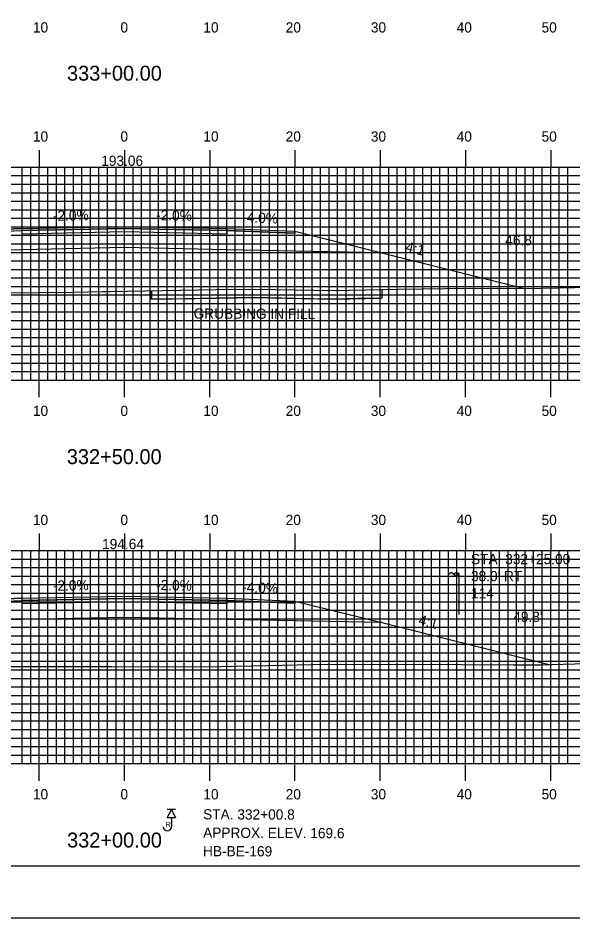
# Model space of a CAD drawing. Extents: x 1822785 to 1823129, y 442591 to 442811.
# Drawn here: x 1822938.8 to 1823003.9, y 442590.5 to 442696.2 of the extents above; entities that cross this region are included whole.
import ezdxf

# ---------------------------------------------------------------- set-up
doc = ezdxf.new("R2010")
doc.units = 0
for name, color, linetype in [('ANNOTATION', 7, 'Continuous'), ('BORDER', 7, 'Continuous'), ('BORING - REFUSAL', 7, 'Continuous'), ('D_Drainage_Text', 7, 'Continuous'), ('D_Roadway_Centerline', 7, 'Continuous'), ('D_Roadway_Centerline_Text', 7, 'Continuous'), ('D_Roadway_Edge_Shoulder', 7, 'Continuous'), ('D_Roadway_Edge_TW', 7, 'Continuous'), ('D_Roadway_Pavement', 7, 'Continuous'), ('D_Roadway_SlopeLines', 7, 'Continuous'), ('D_Roadway_SubGrade', 7, 'Continuous'), ('D_Text_Standard', 7, 'Continuous'), ('D_Utilities_Pole_Joint', 7, 'Continuous'), ('GRUBBING IN FILL', 7, 'Continuous'), ('H_V ANNOTATION', 7, 'Continuous'), ('MAJOR', 7, 'Continuous'), ('MINOR', 7, 'Continuous'), ('PLOT BOUNDARY', 7, 'Continuous'), ('S_Roadway_Centerline', 7, 'Continuous')]:
    doc.layers.add(name, color=color, linetype=linetype)

msp = doc.modelspace()

# ---------------------------------------------------------------- linework, layer by layer
at = {"layer": 'BORDER'}
msp.add_lwpolyline([(1822801.68, 442596.67), (1823121.68, 442596.67), (1823121.68, 442806.67), (1822801.68, 442806.67)], close=True, dxfattribs=at)
at = {"layer": 'BORING - REFUSAL'}
for p, q in [((1822957.26, 442603.27), (1822956.3, 442603.27)), ((1822956.78, 442602.31), (1822956.78, 442601.25))]:
    msp.add_line(p, q, dxfattribs=at)
msp.add_lwpolyline([(1822956.78, 442603.27), (1822957.26, 442602.31), (1822956.3, 442602.31)], close=True, dxfattribs=at)
msp.add_arc((1822956.3, 442601.25), 0.485, 180, 0, dxfattribs=at)
at = {"layer": 'D_Roadway_Centerline'}
for points in [[(1822903.76, 442662.99), (1822919.28, 442668.16), (1822921.11, 442668.62), (1822931.28, 442671.16), (1822939.28, 442671.48), (1822951.28, 442671.72), (1822963.28, 442671.48), (1822971.28, 442671.16), (1822981.46, 442668.62), (1822998.04, 442664.47)], [(1822902.83, 442619.27), (1822919.28, 442624.75), (1822921.11, 442625.21), (1822931.28, 442627.75), (1822939.28, 442628.07), (1822951.28, 442628.31), (1822963.28, 442628.07), (1822971.28, 442627.75), (1822981.46, 442625.21), (1823001.12, 442620.29)]]:
    msp.add_lwpolyline(points, dxfattribs=at)
at = {"layer": 'D_Roadway_Edge_Shoulder'}
for points in [[(1822939.28, 442671.48), (1822931.28, 442671.16), (1822931.28, 442670.91), (1822939.28, 442671.23)], [(1822963.28, 442671.48), (1822971.28, 442671.16), (1822971.28, 442670.91), (1822963.28, 442671.23)], [(1822939.28, 442628.07), (1822931.28, 442627.75), (1822931.28, 442627.5), (1822939.28, 442627.82)], [(1822963.28, 442628.07), (1822971.28, 442627.75), (1822971.28, 442627.5), (1822963.28, 442627.82)]]:
    msp.add_lwpolyline(points, close=True, dxfattribs=at)
at = {"layer": 'D_Roadway_Edge_TW'}
for points in [[(1822939.28, 442671.23), (1822939.28, 442671.48), (1822951.28, 442671.72), (1822963.28, 442671.48), (1822963.28, 442671.23), (1822951.28, 442671.47)], [(1822939.28, 442627.82), (1822939.28, 442628.07), (1822951.28, 442628.31), (1822963.28, 442628.07), (1822963.28, 442627.82), (1822951.28, 442628.06)]]:
    msp.add_lwpolyline(points, close=True, dxfattribs=at)
at = {"layer": 'D_Roadway_Pavement'}
for points in [[(1822939.28, 442670.82), (1822939.28, 442671.23), (1822951.28, 442671.47), (1822963.28, 442671.23), (1822963.28, 442670.82), (1822951.28, 442671.06)], [(1822939.28, 442627.4), (1822939.28, 442627.82), (1822951.28, 442628.06), (1822963.28, 442627.82), (1822963.28, 442627.4), (1822951.28, 442627.64)]]:
    msp.add_lwpolyline(points, close=True, dxfattribs=at)
at = {"layer": 'D_Roadway_SlopeLines'}
for points in [[(1822971.28, 442671.16), (1822981.46, 442668.62), (1822998.04, 442664.47)], [(1822971.28, 442627.75), (1822981.46, 442625.21), (1823001.12, 442620.29)]]:
    msp.add_lwpolyline(points, dxfattribs=at)
at = {"layer": 'D_Roadway_SubGrade'}
for points in [[(1822939.28, 442668.98), (1822921.11, 442668.62), (1822931.28, 442671.16), (1822931.28, 442670.91), (1822939.28, 442671.23), (1822951.28, 442671.47), (1822963.28, 442671.23), (1822971.28, 442670.91), (1822971.28, 442671.16), (1822981.46, 442668.62), (1822963.28, 442668.98), (1822951.28, 442669.22)], [(1822939.28, 442625.57), (1822921.11, 442625.21), (1822931.28, 442627.75), (1822931.28, 442627.5), (1822939.28, 442627.82), (1822951.28, 442628.06), (1822963.28, 442627.82), (1822971.28, 442627.5), (1822971.28, 442627.75), (1822981.46, 442625.21), (1822963.28, 442625.57), (1822951.28, 442625.81)]]:
    msp.add_lwpolyline(points, close=True, dxfattribs=at)
at = {"layer": 'D_Utilities_Pole_Joint'}
for p, q in [((1822989.28, 442630.91), (1822989.44, 442631.02)), ((1822989.75, 442631.02), (1822989.91, 442630.91)), ((1822990.06, 442631.02), (1822989.91, 442630.91)), ((1822990.53, 442630.91), (1822990.38, 442631.02)), ((1822989.28, 442626.15), (1822989.28, 442630.91)), ((1822989.91, 442630.91), (1822990.06, 442630.8)), ((1822990.38, 442630.8), (1822990.53, 442630.91)), ((1822990.53, 442626.15), (1822990.53, 442630.91))]:
    msp.add_line(p, q, dxfattribs=at)
for centre, start, end in [((1822989.59, 442630.8), 90, 125.2644), ((1822989.59, 442630.8), 54.7356, 90), ((1822990.22, 442630.8), 90, 125.2644), ((1822990.22, 442630.8), 54.7356, 90), ((1822990.22, 442631.02), 234.7356, 270), ((1822990.22, 442631.02), 270, 305.2644)]:
    msp.add_arc(centre, 0.271, start, end, dxfattribs=at)
at = {"layer": 'GRUBBING IN FILL'}
for p, q in [((1822954.46, 442664.16), (1822954.46, 442663.16)), ((1822954.46, 442664.16), (1822954.46, 442663.16)), ((1822981.46, 442664.31), (1822981.46, 442663.31)), ((1822981.46, 442664.31), (1822981.46, 442663.31))]:
    msp.add_line(p, q, dxfattribs=at)
msp.add_lwpolyline([(1822954.46, 442664.16), (1822955.79, 442664.19), (1822962.02, 442664.3), (1822966.67, 442664.36), (1822971.21, 442664.27), (1822975.75, 442664.19), (1822979.59, 442664.27), (1822981.46, 442664.31), (1822981.46, 442663.31), (1822978.6, 442663.25), (1822975.75, 442663.19), (1822971.21, 442663.27), (1822966.67, 442663.36), (1822964.35, 442663.33), (1822962.04, 442663.3), (1822958.25, 442663.23), (1822954.46, 442663.16)], close=True, dxfattribs=at)
msp.add_lwpolyline([(1822954.46, 442664.16), (1822955.79, 442664.19), (1822962.02, 442664.3), (1822966.67, 442664.36), (1822971.21, 442664.27), (1822975.75, 442664.19), (1822979.59, 442664.27), (1822981.46, 442664.31), (1822981.46, 442663.31), (1822978.6, 442663.25), (1822975.75, 442663.19), (1822971.21, 442663.27), (1822966.67, 442663.36), (1822964.35, 442663.33), (1822962.04, 442663.3), (1822958.25, 442663.23), (1822954.46, 442663.16)], close=True, dxfattribs=at)
msp.add_lwpolyline([(1822954.46, 442663.16), (1822962.04, 442663.3), (1822966.67, 442663.36), (1822975.75, 442663.19), (1822981.46, 442663.31)], dxfattribs=at)
msp.add_lwpolyline([(1822954.46, 442663.16), (1822962.04, 442663.3), (1822966.67, 442663.36), (1822975.75, 442663.19), (1822981.46, 442663.31)], dxfattribs=at)
at = {"layer": 'MAJOR'}
for p, q in [((1822941.28, 442680.67), (1822941.28, 442678.67)), ((1822951.28, 442680.67), (1822951.28, 442678.67)), ((1822961.28, 442680.67), (1822961.28, 442678.67)), ((1822971.28, 442680.67), (1822971.28, 442678.67)), ((1822981.28, 442680.67), (1822981.28, 442678.67)), ((1822991.28, 442680.67), (1822991.28, 442678.67)), ((1823001.28, 442680.67), (1823001.28, 442678.67)), ((1822811.28, 442678.67), (1823091.28, 442678.67)), ((1822811.28, 442678.67), (1823091.28, 442678.67)), ((1822941.28, 442653.67), (1822941.28, 442678.67)), ((1822951.28, 442653.67), (1822951.28, 442678.67)), ((1822961.28, 442653.67), (1822961.28, 442678.67)), ((1822971.28, 442653.67), (1822971.28, 442678.67)), ((1822981.28, 442653.67), (1822981.28, 442678.67)), ((1822991.28, 442653.67), (1822991.28, 442678.67)), ((1823001.28, 442653.67), (1823001.28, 442678.67)), ((1822811.28, 442673.67), (1823091.28, 442673.67)), ((1822811.28, 442668.67), (1823091.28, 442668.67)), ((1822811.28, 442663.67), (1823091.28, 442663.67)), ((1822811.28, 442658.67), (1823091.28, 442658.67)), ((1822811.28, 442653.67), (1823091.28, 442653.67)), ((1822811.28, 442653.67), (1823091.28, 442653.67)), ((1822941.28, 442651.66), (1822941.28, 442653.67)), ((1822951.28, 442651.66), (1822951.28, 442653.67)), ((1822961.28, 442651.66), (1822961.28, 442653.67)), ((1822971.28, 442651.66), (1822971.28, 442653.67)), ((1822981.28, 442651.66), (1822981.28, 442653.67)), ((1822991.28, 442651.66), (1822991.28, 442653.67)), ((1823001.28, 442651.66), (1823001.28, 442653.67)), ((1822941.28, 442635.67), (1822941.28, 442633.67)), ((1822951.28, 442635.67), (1822951.28, 442633.67)), ((1822961.28, 442635.67), (1822961.28, 442633.67)), ((1822971.28, 442635.67), (1822971.28, 442633.67)), ((1822981.28, 442635.67), (1822981.28, 442633.67)), ((1822991.28, 442635.67), (1822991.28, 442633.67)), ((1823001.28, 442635.67), (1823001.28, 442633.67)), ((1822811.28, 442633.67), (1823091.28, 442633.67)), ((1822811.28, 442633.67), (1823091.28, 442633.67)), ((1822941.28, 442608.67), (1822941.28, 442633.67)), ((1822951.28, 442608.67), (1822951.28, 442633.67)), ((1822961.28, 442608.67), (1822961.28, 442633.67)), ((1822971.28, 442608.67), (1822971.28, 442633.67)), ((1822981.28, 442608.67), (1822981.28, 442633.67)), ((1822991.28, 442608.67), (1822991.28, 442633.67)), ((1823001.28, 442608.67), (1823001.28, 442633.67)), ((1822811.28, 442628.67), (1823091.28, 442628.67)), ((1822811.28, 442623.67), (1823091.28, 442623.67)), ((1822811.28, 442618.67), (1823091.28, 442618.67)), ((1822811.28, 442613.67), (1823091.28, 442613.67)), ((1822811.28, 442608.67), (1823091.28, 442608.67)), ((1822811.28, 442608.67), (1823091.28, 442608.67)), ((1822941.28, 442606.66), (1822941.28, 442608.67)), ((1822951.28, 442606.66), (1822951.28, 442608.67)), ((1822961.28, 442606.66), (1822961.28, 442608.67)), ((1822971.28, 442606.66), (1822971.28, 442608.67)), ((1822981.28, 442606.66), (1822981.28, 442608.67)), ((1822991.28, 442606.66), (1822991.28, 442608.67)), ((1823001.28, 442606.66), (1823001.28, 442608.67))]:
    msp.add_line(p, q, dxfattribs=at)
at = {"layer": 'MINOR'}
for p, q in [((1822939.28, 442653.67), (1822939.28, 442678.67)), ((1822940.28, 442653.67), (1822940.28, 442678.67)), ((1822942.28, 442653.67), (1822942.28, 442678.67)), ((1822943.28, 442653.67), (1822943.28, 442678.67)), ((1822944.28, 442653.67), (1822944.28, 442678.67)), ((1822945.28, 442653.67), (1822945.28, 442678.67)), ((1822946.28, 442653.67), (1822946.28, 442678.67)), ((1822947.28, 442653.67), (1822947.28, 442678.67)), ((1822948.28, 442653.67), (1822948.28, 442678.67)), ((1822949.28, 442653.67), (1822949.28, 442678.67)), ((1822950.28, 442653.67), (1822950.28, 442678.67)), ((1822952.28, 442653.67), (1822952.28, 442678.67)), ((1822953.28, 442653.67), (1822953.28, 442678.67)), ((1822954.28, 442653.67), (1822954.28, 442678.67)), ((1822955.28, 442653.67), (1822955.28, 442678.67)), ((1822956.28, 442653.67), (1822956.28, 442678.67)), ((1822957.28, 442653.67), (1822957.28, 442678.67)), ((1822958.28, 442653.67), (1822958.28, 442678.67)), ((1822959.28, 442653.67), (1822959.28, 442678.67)), ((1822960.28, 442653.67), (1822960.28, 442678.67)), ((1822962.28, 442653.67), (1822962.28, 442678.67)), ((1822963.28, 442653.67), (1822963.28, 442678.67)), ((1822964.28, 442653.67), (1822964.28, 442678.67)), ((1822965.28, 442653.67), (1822965.28, 442678.67)), ((1822966.28, 442653.67), (1822966.28, 442678.67)), ((1822967.28, 442653.67), (1822967.28, 442678.67)), ((1822968.28, 442653.67), (1822968.28, 442678.67)), ((1822969.28, 442653.67), (1822969.28, 442678.67)), ((1822970.28, 442653.67), (1822970.28, 442678.67)), ((1822972.28, 442653.67), (1822972.28, 442678.67)), ((1822973.28, 442653.67), (1822973.28, 442678.67)), ((1822974.28, 442653.67), (1822974.28, 442678.67)), ((1822975.28, 442653.67), (1822975.28, 442678.67)), ((1822976.28, 442653.67), (1822976.28, 442678.67)), ((1822977.28, 442653.67), (1822977.28, 442678.67)), ((1822978.28, 442653.67), (1822978.28, 442678.67)), ((1822979.28, 442653.67), (1822979.28, 442678.67)), ((1822980.28, 442653.67), (1822980.28, 442678.67)), ((1822982.28, 442653.67), (1822982.28, 442678.67)), ((1822983.28, 442653.67), (1822983.28, 442678.67)), ((1822984.28, 442653.67), (1822984.28, 442678.67)), ((1822985.28, 442653.67), (1822985.28, 442678.67)), ((1822986.28, 442653.67), (1822986.28, 442678.67)), ((1822987.28, 442653.67), (1822987.28, 442678.67)), ((1822988.28, 442653.67), (1822988.28, 442678.67)), ((1822989.28, 442653.67), (1822989.28, 442678.67)), ((1822990.28, 442653.67), (1822990.28, 442678.67)), ((1822992.28, 442653.67), (1822992.28, 442678.67)), ((1822993.28, 442653.67), (1822993.28, 442678.67)), ((1822994.28, 442653.67), (1822994.28, 442678.67)), ((1822995.28, 442653.67), (1822995.28, 442678.67)), ((1822996.28, 442653.67), (1822996.28, 442678.67)), ((1822997.28, 442653.67), (1822997.28, 442678.67)), ((1822998.28, 442653.67), (1822998.28, 442678.67)), ((1822999.28, 442653.67), (1822999.28, 442678.67)), ((1823000.28, 442653.67), (1823000.28, 442678.67)), ((1823002.28, 442653.67), (1823002.28, 442678.67)), ((1823003.28, 442653.67), (1823003.28, 442678.67)), ((1822811.28, 442677.67), (1823091.28, 442677.67)), ((1822811.28, 442676.67), (1823091.28, 442676.67)), ((1822811.28, 442675.67), (1823091.28, 442675.67)), ((1822811.28, 442674.67), (1823091.28, 442674.67)), ((1822811.28, 442672.67), (1823091.28, 442672.67)), ((1822811.28, 442671.67), (1823091.28, 442671.67)), ((1822811.28, 442670.67), (1823091.28, 442670.67)), ((1822811.28, 442669.67), (1823091.28, 442669.67)), ((1822811.28, 442667.67), (1823091.28, 442667.67)), ((1822811.28, 442666.67), (1823091.28, 442666.67)), ((1822811.28, 442665.67), (1823091.28, 442665.67)), ((1822811.28, 442664.67), (1823091.28, 442664.67)), ((1822811.28, 442662.67), (1823091.28, 442662.67)), ((1822811.28, 442661.67), (1823091.28, 442661.67)), ((1822811.28, 442660.67), (1823091.28, 442660.67)), ((1822811.28, 442659.67), (1823091.28, 442659.67)), ((1822811.28, 442657.67), (1823091.28, 442657.67)), ((1822811.28, 442656.67), (1823091.28, 442656.67)), ((1822811.28, 442655.67), (1823091.28, 442655.67)), ((1822811.28, 442654.67), (1823091.28, 442654.67)), ((1822939.28, 442608.67), (1822939.28, 442633.67)), ((1822940.28, 442608.67), (1822940.28, 442633.67)), ((1822942.28, 442608.67), (1822942.28, 442633.67)), ((1822943.28, 442608.67), (1822943.28, 442633.67)), ((1822944.28, 442608.67), (1822944.28, 442633.67)), ((1822945.28, 442608.67), (1822945.28, 442633.67)), ((1822946.28, 442608.67), (1822946.28, 442633.67)), ((1822947.28, 442608.67), (1822947.28, 442633.67)), ((1822948.28, 442608.67), (1822948.28, 442633.67)), ((1822949.28, 442608.67), (1822949.28, 442633.67)), ((1822950.28, 442608.67), (1822950.28, 442633.67)), ((1822952.28, 442608.67), (1822952.28, 442633.67)), ((1822953.28, 442608.67), (1822953.28, 442633.67)), ((1822954.28, 442608.67), (1822954.28, 442633.67)), ((1822955.28, 442608.67), (1822955.28, 442633.67)), ((1822956.28, 442608.67), (1822956.28, 442633.67)), ((1822957.28, 442608.67), (1822957.28, 442633.67)), ((1822958.28, 442608.67), (1822958.28, 442633.67)), ((1822959.28, 442608.67), (1822959.28, 442633.67)), ((1822960.28, 442608.67), (1822960.28, 442633.67)), ((1822962.28, 442608.67), (1822962.28, 442633.67)), ((1822963.28, 442608.67), (1822963.28, 442633.67)), ((1822964.28, 442608.67), (1822964.28, 442633.67)), ((1822965.28, 442608.67), (1822965.28, 442633.67)), ((1822966.28, 442608.67), (1822966.28, 442633.67)), ((1822967.28, 442608.67), (1822967.28, 442633.67)), ((1822968.28, 442608.67), (1822968.28, 442633.67)), ((1822969.28, 442608.67), (1822969.28, 442633.67)), ((1822970.28, 442608.67), (1822970.28, 442633.67)), ((1822972.28, 442608.67), (1822972.28, 442633.67)), ((1822973.28, 442608.67), (1822973.28, 442633.67)), ((1822974.28, 442608.67), (1822974.28, 442633.67)), ((1822975.28, 442608.67), (1822975.28, 442633.67)), ((1822976.28, 442608.67), (1822976.28, 442633.67)), ((1822977.28, 442608.67), (1822977.28, 442633.67)), ((1822978.28, 442608.67), (1822978.28, 442633.67)), ((1822979.28, 442608.67), (1822979.28, 442633.67)), ((1822980.28, 442608.67), (1822980.28, 442633.67)), ((1822982.28, 442608.67), (1822982.28, 442633.67)), ((1822983.28, 442608.67), (1822983.28, 442633.67)), ((1822984.28, 442608.67), (1822984.28, 442633.67)), ((1822985.28, 442608.67), (1822985.28, 442633.67)), ((1822986.28, 442608.67), (1822986.28, 442633.67)), ((1822987.28, 442608.67), (1822987.28, 442633.67)), ((1822988.28, 442608.67), (1822988.28, 442633.67)), ((1822989.28, 442608.67), (1822989.28, 442633.67)), ((1822990.28, 442608.67), (1822990.28, 442633.67)), ((1822992.28, 442608.67), (1822992.28, 442633.67)), ((1822993.28, 442608.67), (1822993.28, 442633.67)), ((1822994.28, 442608.67), (1822994.28, 442633.67)), ((1822995.28, 442608.67), (1822995.28, 442633.67)), ((1822996.28, 442608.67), (1822996.28, 442633.67)), ((1822997.28, 442608.67), (1822997.28, 442633.67)), ((1822998.28, 442608.67), (1822998.28, 442633.67)), ((1822999.28, 442608.67), (1822999.28, 442633.67)), ((1823000.28, 442608.67), (1823000.28, 442633.67)), ((1823002.28, 442608.67), (1823002.28, 442633.67)), ((1823003.28, 442608.67), (1823003.28, 442633.67)), ((1822811.28, 442632.67), (1823091.28, 442632.67)), ((1822811.28, 442631.67), (1823091.28, 442631.67)), ((1822811.28, 442630.67), (1823091.28, 442630.67)), ((1822811.28, 442629.67), (1823091.28, 442629.67)), ((1822811.28, 442627.67), (1823091.28, 442627.67)), ((1822811.28, 442626.67), (1823091.28, 442626.67)), ((1822811.28, 442625.67), (1823091.28, 442625.67)), ((1822811.28, 442624.67), (1823091.28, 442624.67)), ((1822811.28, 442622.67), (1823091.28, 442622.67)), ((1822811.28, 442621.67), (1823091.28, 442621.67)), ((1822811.28, 442620.67), (1823091.28, 442620.67)), ((1822811.28, 442619.67), (1823091.28, 442619.67)), ((1822811.28, 442617.67), (1823091.28, 442617.67)), ((1822811.28, 442616.67), (1823091.28, 442616.67)), ((1822811.28, 442615.67), (1823091.28, 442615.67)), ((1822811.28, 442614.67), (1823091.28, 442614.67)), ((1822811.28, 442612.67), (1823091.28, 442612.67)), ((1822811.28, 442611.67), (1823091.28, 442611.67)), ((1822811.28, 442610.67), (1823091.28, 442610.67)), ((1822811.28, 442609.67), (1823091.28, 442609.67))]:
    msp.add_line(p, q, dxfattribs=at)
at = {"layer": 'PLOT BOUNDARY'}
msp.add_lwpolyline([(1822785.5, 442590.55), (1823125.5, 442590.55), (1823125.5, 442810.55), (1822785.5, 442810.55)], close=True, dxfattribs=at)
at = {"layer": 'S_Roadway_Centerline'}
for points in [[(1822896.35, 442663.67), (1822899.55, 442663.09), (1822900.08, 442663.01), (1822900.21, 442663), (1822901.21, 442662.99), (1822910.69, 442662.97), (1822910.77, 442662.9), (1822931.67, 442663.75), (1822932.25, 442663.82), (1822933.55, 442663.86), (1822945.21, 442664.01), (1822948.74, 442664.06), (1822949.55, 442664.07), (1822962.02, 442664.3), (1822966.67, 442664.36), (1822975.75, 442664.19), (1822983.42, 442664.35), (1822988.9, 442664.44), (1823000.16, 442664.48), (1823006.05, 442664.59)], [(1822897.57, 442619.14), (1822900.15, 442619.12), (1822905.36, 442619.4), (1822911.52, 442619.6), (1822921.49, 442619.78), (1822928.3, 442619.99), (1822932.35, 442620.05), (1822945.24, 442620.07), (1822949.76, 442620.06), (1822959.75, 442620.04), (1822962.6, 442620.07), (1822973.3, 442620.28), (1822979.45, 442620.33), (1822990.81, 442620.28), (1822996.89, 442620.26), (1823000.09, 442620.26), (1823013.45, 442620.66)]]:
    msp.add_lwpolyline(points, dxfattribs=at)

# ---------------------------------------------------------------- texts
at = {"layer": 'ANNOTATION'}
for s, rotation, p in [('-2.0%', 1.1458, (1822942.89, 442672.36)), ('-2.0%', 358.8542, (1822954.97, 442672.45)), ('-4.0%', 357.7094, (1822965.07, 442672.21)), ('4:1', 345.9638, (1822984.17, 442668.8)), ('-2.0%', 1.1458, (1822942.89, 442628.94)), ('-2.0%', 358.8542, (1822954.97, 442629.04)), ('-4.0%', 357.7094, (1822965.07, 442628.8)), ('4:1', 345.9638, (1822985.7, 442625))]:
    msp.add_text(s, height=1.2, rotation=rotation, dxfattribs=at).set_placement(p)
at = {"layer": 'BORING - REFUSAL'}
for s, p in [('STA. 332+00.8', (1822960.5, 442602.12)), ('APPROX. ELEV. 169.6', (1822960.5, 442599.96)), ('HB-BE-169', (1822960.49, 442597.8))]:
    msp.add_text(s, height=1.2, rotation=359.8142, dxfattribs=at).set_placement(p)
msp.add_text('R', height=0.64, dxfattribs=at).set_placement((1822956.07, 442601.19))
at = {"layer": 'D_Drainage_Text'}
for s, p in [('STA. 332+25.00', (1822991.93, 442632.07)), ("38.0' RT", (1822991.93, 442630.07)), ('114', (1822991.93, 442628.06))]:
    msp.add_text(s, height=1.2, dxfattribs=at).set_placement(p)
at = {"layer": 'D_Roadway_Centerline'}
for s, p in [('C', (1822951.28, 442671.72)), ('L', (1822951.28, 442671.72)), ('C', (1822951.28, 442628.31)), ('L', (1822951.28, 442628.3))]:
    msp.add_text(s, height=0.0146, dxfattribs=at).set_placement(p)
at = {"layer": 'D_Roadway_Centerline_Text'}
for s, p in [('193.06', (1822948.55, 442678.82)), ('194.64', (1822948.65, 442633.84))]:
    msp.add_text(s, height=1.2, dxfattribs=at).set_placement(p)
at = {"layer": 'D_Text_Standard'}
for s, p in [("46.8'", (1822995.95, 442669.51)), ("49.8'", (1822996.89, 442625.29))]:
    msp.add_text(s, height=1.2, dxfattribs=at).set_placement(p)
at = {"layer": 'GRUBBING IN FILL'}
msp.add_text('GRUBBING IN FILL', height=1.2, rotation=359.8053, dxfattribs=at).set_placement((1822959.39, 442660.89))
at = {"layer": 'H_V ANNOTATION'}
for s, height, p in [('10', 1.2, (1822940.53, 442694.47)), ('0', 1.2, (1822950.8, 442694.47)), ('10', 1.2, (1822960.53, 442694.47)), ('20', 1.2, (1822970.19, 442694.47)), ('30', 1.2, (1822980.18, 442694.47)), ('40', 1.2, (1822990.25, 442694.47)), ('50', 1.2, (1823000.21, 442694.47)), ('333+00.00', 1.75, (1822944.53, 442688.82)), ('10', 1.2, (1822940.53, 442681.67)), ('0', 1.2, (1822950.8, 442681.67)), ('10', 1.2, (1822960.53, 442681.67)), ('20', 1.2, (1822970.19, 442681.67)), ('30', 1.2, (1822980.18, 442681.67)), ('40', 1.2, (1822990.25, 442681.67)), ('50', 1.2, (1823000.21, 442681.67)), ('10', 1.2, (1822940.53, 442649.47)), ('0', 1.2, (1822950.8, 442649.47)), ('10', 1.2, (1822960.53, 442649.47)), ('20', 1.2, (1822970.19, 442649.47)), ('30', 1.2, (1822980.18, 442649.47)), ('40', 1.2, (1822990.25, 442649.47)), ('50', 1.2, (1823000.21, 442649.47)), ('332+50.00', 1.75, (1822944.51, 442643.82)), ('10', 1.2, (1822940.53, 442636.67)), ('0', 1.2, (1822950.8, 442636.67)), ('10', 1.2, (1822960.53, 442636.67)), ('20', 1.2, (1822970.19, 442636.67)), ('30', 1.2, (1822980.18, 442636.67)), ('40', 1.2, (1822990.25, 442636.67)), ('50', 1.2, (1823000.21, 442636.67)), ('10', 1.2, (1822940.53, 442604.47)), ('0', 1.2, (1822950.8, 442604.47)), ('10', 1.2, (1822960.53, 442604.47)), ('20', 1.2, (1822970.19, 442604.47)), ('30', 1.2, (1822980.18, 442604.47)), ('40', 1.2, (1822990.25, 442604.47)), ('50', 1.2, (1823000.21, 442604.47)), ('332+00.00', 1.75, (1822944.54, 442598.82))]:
    msp.add_text(s, height=height, dxfattribs=at).set_placement(p)

doc.saveas('drawing.dxf')
